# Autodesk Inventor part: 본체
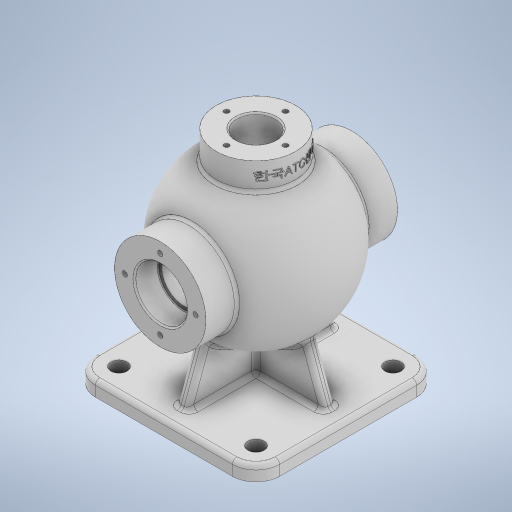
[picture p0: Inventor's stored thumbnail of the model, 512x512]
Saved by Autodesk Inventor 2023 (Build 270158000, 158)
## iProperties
Created: 2023-07
Part Number: 본체
Material: 일반
Document SubType Name: Modeling
Designer: Owner
Density: 1 g/cm^3
Appearance: 기본값
Author: Owner
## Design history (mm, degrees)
sketch "스케치1"
  geometry: L1 (62.5, 62.5)-(-62.5, 62.5); L2 (-62.5, 62.5)-(-62.5, -62.5); L3 (-62.5, -62.5)-(62.5, -62.5); L4 (62.5, -62.5)-(62.5, 62.5); L5 (62.5, 62.5)-(-62.5, -62.5); L6 (-62.5, 62.5)-(62.5, -62.5); 1 further point
  constraints: 12 end point, 2 midpoint, 2 parallel, 2 perpendicular, 1 horizontal
  dimensions: "d0" = 125 distance of L2.end L3.end
extrude "돌출1" new body sketch "스케치1" distance "d1" = 10; taper "d2" = 0 deg
sketch "스케치2"
  geometry: L1 (0, 62.5)-(0, -62.5) reference; L2 (85, 54)-(85, -54); A1 r 54 centre (85, 0) between (85, -54) and (85, 54); 4 further points
  constraints: 3 midpoint, 2 end point, 2 point on circle, 1 centre point, 1 coincident, 1 horizontal alignment, 1 vertical
  dimensions: "d3" = 108 diameter of A1; "d4" = 85 distance of point (0, 0) point (85, 0)
revolve "회전1" sketch "스케치2" stored, may be unused: angle "d5" = 90 deg
sketch "스케치3"
  geometry: L1 (62.5, 10)-(62.5, 0) reference; L2 (62.5, 0)-(-62.5, 0) reference; L3 (-62.5, 0)-(-62.5, 10) reference; L4 (-62.5, 10)-(62.5, 10) reference; C1 r 54 at (0, 85) reference; C2 r 31 at (0, 85); 1 further point
  constraints: 1 centre point, 1 coincident
  dimensions: "d6" = 62 diameter of C2
extrude "돌출2" join sketch "스케치3" stored distance "d7" = 130; taper "d8" = 0 deg
node "작업 평면1"
sketch "스케치4"
  geometry: C1 r 27 at (0, 0); 1 further point
  constraints: 1 centre point, 1 coincident
  dimensions: "d10" = 54 diameter of C1
extrude "돌출3" join sketch "스케치4" stored distance "d11" = 130; taper "d12" = 0 deg
sketch "스케치5"
  geometry: L1 (54, 44.215)-(54, 65) reference; L2 (54, 65)-(116, 65) reference; L3 (116, 65)-(116, 44.215) reference; L4 (131.765, 27)-(150, 27) reference; L5 (150, 27)-(150, -27) reference; L6 (150, -27)-(131.765, -27) reference; L7 (116, -44.215)-(116, -65) reference; L8 (116, -65)-(54, -65) reference; L9 (54, -65)-(54, -44.215) reference; L10 (0, 62.5)-(10, 62.5) reference; L11 (10, 62.5)-(10, -62.5) reference; L12 (10, -62.5)-(0, -62.5) reference; L13 (0, -62.5)-(0, 62.5) reference; L14 (10, -62.5)-(10, 62.5) reference; L15 (10, 50.5)-(80, 25.022); L16 (80, 25.022)-(80, -25.022); L17 (80, -25.022)-(10, -50.5); A1 r 54 centre (85, 0) between (54, 44.215) and (54, -44.215) reference; A2 r 54 centre (85, 0) between (131.765, 27) and (116, 44.215) reference; A3 r 54 centre (85, 0) between (116, -44.215) and (131.765, -27) reference; 5 further points
  constraints: 6 end point, 2 point on line, 1 parallel
  dimensions: "d13" = 12 distance from line of L10 L15.start; "d14" = 20 deg angle of L10 L15; "d15" = 20 deg angle of L12 L17; "d16" = 12 distance of L11.end L17.end; "d17" = 80 distance between parallel lines of L13 L16
extrude "돌출4" join sketch "스케치5" stored distance "d18" = 8; taper "d19" = 0 deg
sketch "스케치6"
  geometry: L1 (-27, 131.765)-(-27, 150) reference; L2 (-27, 150)-(27, 150) reference; L3 (27, 150)-(27, 131.765) reference; L4 (-4, 10)-(-4, 31.148) reference; L5 (-62.5, 10)-(-4, 10) reference; L6 (-62.5, 0)-(-62.5, 10) reference; L7 (62.5, 0)-(-62.5, 0) reference; L8 (62.5, 10)-(62.5, 0) reference; L9 (4, 10)-(62.5, 10) reference; L10 (4, 31.148)-(4, 10) reference; L11 (62.5, 10)-(-62.5, 10) reference; L12 (50.5, 10)-(42.103, 33.069); A1 r 54 centre (0, 85) between (4, 31.148) and (27, 131.765) reference; A2 r 54 centre (0, 85) between (-27, 131.765) and (-4, 31.148) reference; 1 further point
  constraints: 2 end point, 1 point on line
  dimensions: "d20" = 12 distance of L8.start L12.start; "d21" = 20 deg angle of L8 L12
feature "리브1" sketch "스케치6" dims "d22" = 1, "d23" = 8, "d24" = 0, "d25" = 0, "d26" = 1, "d27" = 1
sketch "스케치7"
  geometry: L1 (46.034, -37.385)-(10, -50.5) reference; L2 (10, -50.5)-(10, -62.5) reference; L3 (10, -62.5)-(0, -62.5) reference; L4 (0, -62.5)-(0, 62.5) reference; L5 (0, 62.5)-(10, 62.5) reference; L6 (10, 62.5)-(10, 50.5) reference; L7 (10, 50.5)-(46.034, 37.385) reference; L8 (116, -44.215)-(116, -65) reference; L9 (116, -65)-(54, -65) reference; L10 (54, -65)-(54, -44.215) reference; L11 (150, -27)-(131.765, -27) reference; L12 (150, 27)-(150, -27) reference; L13 (131.765, 27)-(150, 27) reference; L14 (54, 44.215)-(54, 65) reference; L15 (54, 65)-(116, 65) reference; L16 (116, 65)-(116, 44.215) reference; L17 (85, 44)-(85, -44); L18 (54, -44.215)-(116, -44.215) reference; A1 r 54 centre (85, 0) between (116, -44.215) and (131.765, -27) reference; A2 r 54 centre (85, 0) between (46.034, -37.385) and (54, -44.215) reference; A3 r 54 centre (85, 0) between (54, 44.215) and (46.034, 37.385) reference; A4 r 54 centre (85, 0) between (131.765, 27) and (116, 44.215) reference; A5 r 44 centre (85, 0) between (85, -44) and (85, 44); 1 further point
  constraints: 2 end point, 2 point on circle, 1 centre point, 1 coincident, 1 midpoint, 1 perpendicular
  dimensions: "d28" = 88 diameter of A5
revolve "회전2" sketch "스케치7" stored, may be unused: angle "d29" = 90 deg
sketch "스케치8"
  geometry: C1 r 31 at (0, 0) reference; C2 r 17.5 at (0, 0); 1 further point
  constraints: 1 centre point, 1 coincident
  dimensions: "d30" = 35 diameter of C2
extrude "돌출5" cut sketch "스케치8" distance "d31" = 16; taper "d32" = 0 deg
sketch "스케치9"
  geometry: C1 r 17.5 at (0, 0) reference; C2 r 15 at (0, 0); 1 further point
  constraints: 1 centre point, 1 coincident
  dimensions: "d33" = 30 diameter of C2
extrude "돌출6" cut sketch "스케치9" extent not by distance; stored distance "d34" = 16; taper "d35" = 0 deg
sketch "스케치10"
  geometry: C1 r 17.5 at (0, 0) reference; 2 further points
  constraints: 1 vertical alignment
  dimensions: "d36" = 24 distance of C1.centre point (0, 24)
hole "구멍1" sketch "스케치10" at (0, 24) diameter "d37" = 3.45873; stored, may be unused: countersink angle "d41" = 90 deg, drill point angle "d43" = 118 deg; dims "d38" = 12, "d39" = 8, "d40" = 4.4, "d42" = 15
sketch "스케치11"
  geometry: C1 r 27 at (0, 0) reference; C2 r 13 at (0, 0)
  constraints: 1 centre point, 1 coincident
  dimensions: "d47" = 26 diameter of C2
extrude "돌출7" cut sketch "스케치11" stored distance "d48" = 10; taper "d49" = 0 deg
sketch "스케치12"
  geometry: C1 r 13 at (0, 0) reference; 1 further point
  constraints: 1 vertical alignment
  dimensions: "d50" = 20 distance of C1.centre point (0, 20)
hole "구멍2" sketch "스케치12" at (0, 20) diameter "d51" = 3.45873; stored, may be unused: countersink angle "d55" = 90 deg, drill point angle "d57" = 118 deg; dims "d52" = 9, "d53" = 4, "d54" = 2, "d56" = 11
fillet "모깎기1" dims "d61" = 16
sketch "스케치13"
  geometry: C1 r 5.5 at (46.5, -46.5); A1 r 16 centre (46.5, -46.5) between (46.5, -62.5) and (62.5, -46.5) reference; 1 further point
  constraints: 1 centre point, 1 coincident
  dimensions: "d62" = 11 diameter of C1
extrude "돌출8" cut sketch "스케치13" extent not by distance; stored distance "d63" = 0; taper "d64" = 0 deg
fillet "모깎기2" dims "d68" = 3
fillet "모깎기3" dims "d69" = 3
fillet "모깎기4" dims "d70" = 3
fillet "모깎기5" dims "d71" = 3
fillet "모깎기6" dims "d72" = 0.6
chamfer "모따기1" distance "d73" = 1; stored, may be unused: second distance "d74" = 2, angle "d75" = 45 deg
node "작업 평면2"
sketch "스케치14"
  geometry: L1 (150, 27)-(150, -27) reference; L2 (-30, 0)-(180, 0) reference; 2 further points
  constraints: 1 point on line, 1 other
  dimensions: "d77" = 9 distance from line of L1 point (141, 0)
feature "엠보싱1" sketch "스케치14" dims "d78" = 0.5, "d79" = 0
fillet "모깎기7" dims "d80" = 3
feature "ρ耀σ耀υ耀χ耀ω耀ϋ耀ύ耀Ϗ耀" dims "d0" = 125, "d1" = 10, "d2" = 0, "d3" = 108, "d4" = 85, "d5" = 90 deg, "d6" = 62, "d7" = 130, "d8" = 0, "d9" = -150, "d10" = 54, "d11" = 130, "d12" = 0, "d13" = 12, "d14" = 20 deg, "d15" = 20 deg, "d16" = 12, "d17" = 80, "d18" = 8, "d19" = 0, "d20" = 12, "d21" = 20 deg, "d22" = 1, "d23" = 8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
node "솔리드1"
mirror "미러1"
mirror "미러2"
pattern_circular "원형 패턴1" dims angle "d45" = 360 deg
mirror "미러3"
pattern_circular "원형 패턴2" dims angle "d59" = 360 deg
pattern_circular "원형 패턴3" dims angle "d66" = 360 deg
node "절단 모서리 투영1"
node "절단 모서리 투영2"
node "절단 모서리 투영3"
node "절단 모서리 투영4"
feature "A9D066F2-1C7D-4E18-AEED-F7BC21143FA4" dims "d37" = 3.45873, "d38" = 12, "d39" = 8, "d40" = 4.4, "d41" = 90 deg, "d42" = 15, "d43" = 118 deg
